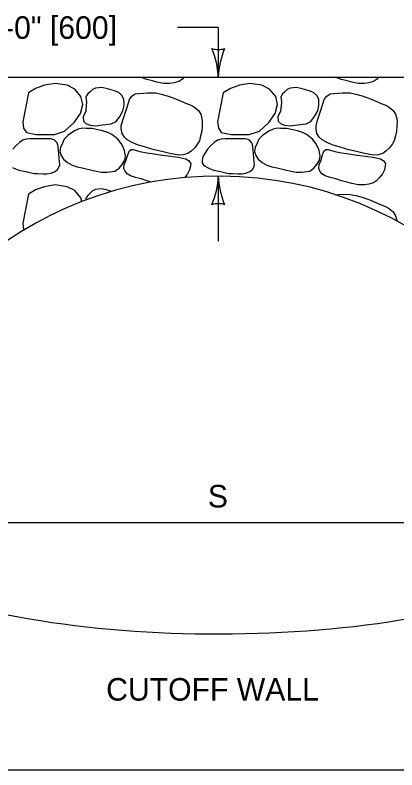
# Model space of a CAD drawing. Extents: x 49991.4 to 50021, y 49987.6 to 50011.4.
# Drawn here: x 50001.991 to 50003.007, y 50007.835 to 50009.843 of the extents above; entities that cross this region are included whole.
import ezdxf

# ---------------------------------------------------------------- set-up
doc = ezdxf.new("R2010")
doc.units = 0
for name, color, linetype in [('Default', 7, 'Continuous'), ('Level 1', 7, 'Continuous'), ('Level 2', 7, 'Continuous'), ('Level 3', 7, 'Continuous')]:
    doc.layers.add(name, color=color, linetype=linetype)

msp = doc.modelspace()

# ---------------------------------------------------------------- linework, layer by layer
at = {"layer": 'Default'}
for points in [[(50002.4399, 50009.6783), (50002.4344, 50009.6723), (50002.4262, 50009.6671), (50002.4139, 50009.6633), (50002.4024, 50009.6611), (50002.386, 50009.6615), (50002.3683, 50009.6648), (50002.3564, 50009.6686), (50002.3412, 50009.6723), (50002.326, 50009.6775), (50002.3229, 50009.6783)], [(50002.9581, 50009.6783), (50002.9526, 50009.6723), (50002.9444, 50009.6671), (50002.9321, 50009.6633), (50002.9206, 50009.6611), (50002.9042, 50009.6615), (50002.8866, 50009.6648), (50002.8747, 50009.6686), (50002.8595, 50009.6723), (50002.8443, 50009.6775), (50002.8412, 50009.6783)], [(50001.9842, 50009.4377), (50001.992, 50009.4347), (50002.001, 50009.4309), (50002.0101, 50009.4287), (50002.0191, 50009.4272), (50002.0298, 50009.4242), (50002.0417, 50009.422), (50002.0515, 50009.422), (50002.0655, 50009.4212), (50002.0757, 50009.4212), (50002.0868, 50009.4227), (50002.0975, 50009.4272), (50002.104, 50009.4324), (50002.1077, 50009.4384), (50002.1098, 50009.4451), (50002.1081, 50009.4627), (50002.1069, 50009.475), (50002.1061, 50009.4839), (50002.1044, 50009.4992), (50002.1008, 50009.5056), (50002.095, 50009.5112), (50002.0852, 50009.5138), (50002.0733, 50009.5142), (50002.0581, 50009.5145), (50002.0429, 50009.5145), (50002.0314, 50009.5145), (50002.0207, 50009.5134), (50002.0113, 50009.5104), (50002.0027, 50009.5041), (50001.9928, 50009.4959), (50001.9846, 50009.4865)], [(50002.3546, 50009.3993), (50002.3412, 50009.4026), (50002.326, 50009.4078), (50002.3109, 50009.4115), (50002.2977, 50009.416), (50002.2891, 50009.4209), (50002.2834, 50009.428), (50002.2805, 50009.4354), (50002.2813, 50009.4459), (50002.2858, 50009.4556), (50002.2899, 50009.4686), (50002.2944, 50009.4813), (50002.2994, 50009.4854), (50002.3055, 50009.4862), (50002.3232, 50009.4809), (50002.3412, 50009.4772), (50002.3552, 50009.475), (50002.3708, 50009.4727), (50002.3831, 50009.4705), (50002.3979, 50009.469), (50002.4245, 50009.4653), (50002.445, 50009.4608), (50002.4524, 50009.4563), (50002.4582, 50009.4489), (50002.4574, 50009.4414), (50002.4553, 50009.4313), (50002.45, 50009.4212), (50002.4426, 50009.4115), (50002.4421, 50009.411)], [(50002.1685, 50009.3471), (50002.1662, 50009.3571), (50002.1498, 50009.3765), (50002.1293, 50009.3869), (50002.0973, 50009.3914), (50002.0694, 50009.3869), (50002.0456, 50009.3787), (50002.0265, 50009.3671), (50002.0185, 50009.3264), (50002.0111, 50009.2899), (50002.0135, 50009.2727), (50002.0143, 50009.2715)], [(50002.2478, 50009.3741), (50002.237, 50009.3772), (50002.2218, 50009.3813), (50002.2046, 50009.3794), (50002.1968, 50009.3757), (50002.1898, 50009.369), (50002.1841, 50009.3638), (50002.1795, 50009.3559), (50002.1801, 50009.3515)], [(50002.8432, 50009.3655), (50002.8517, 50009.3657), (50002.8615, 50009.3668), (50002.8824, 50009.3664), (50002.8976, 50009.3635), (50002.914, 50009.359), (50002.9272, 50009.3545), (50002.9362, 50009.3508), (50002.951, 50009.3448), (50002.9649, 50009.3388), (50002.9793, 50009.3336), (50002.9875, 50009.328), (50002.9973, 50009.3202), (50003.0031, 50009.3097), (50003.0064, 50009.2974), (50003.0065, 50009.2956)]]:
    msp.add_lwpolyline(points, dxfattribs=at)
for points in [[(50002.0265, 50009.6368), (50002.0185, 50009.5962), (50002.0111, 50009.5596), (50002.0135, 50009.5424), (50002.0209, 50009.5312), (50002.0472, 50009.5253), (50002.0956, 50009.5253), (50002.1227, 50009.535), (50002.1481, 50009.5574), (50002.1646, 50009.5813), (50002.1711, 50009.6059), (50002.1662, 50009.6268), (50002.1498, 50009.6462), (50002.1293, 50009.6566), (50002.0973, 50009.6611), (50002.0694, 50009.6566), (50002.0456, 50009.6484)], [(50002.2046, 50009.6492), (50002.1968, 50009.6454), (50002.1898, 50009.6387), (50002.1841, 50009.6335), (50002.1795, 50009.6257), (50002.1812, 50009.6126), (50002.1804, 50009.6033), (50002.1787, 50009.588), (50002.1722, 50009.5727), (50002.1726, 50009.5611), (50002.1787, 50009.5548), (50002.1894, 50009.5503), (50002.205, 50009.5484), (50002.2239, 50009.551), (50002.2468, 50009.554), (50002.26, 50009.5607), (50002.2694, 50009.5738), (50002.278, 50009.5883), (50002.2809, 50009.6029), (50002.2805, 50009.6193), (50002.2752, 50009.6298), (50002.2669, 50009.6376), (50002.255, 50009.6417), (50002.237, 50009.6469), (50002.2218, 50009.651)], [(50002.5448, 50009.6368), (50002.5367, 50009.5962), (50002.5293, 50009.5596), (50002.5318, 50009.5424), (50002.5392, 50009.5312), (50002.5654, 50009.5253), (50002.6139, 50009.5253), (50002.641, 50009.535), (50002.6664, 50009.5574), (50002.6828, 50009.5813), (50002.6894, 50009.6059), (50002.6845, 50009.6268), (50002.668, 50009.6462), (50002.6475, 50009.6566), (50002.6155, 50009.6611), (50002.5876, 50009.6566), (50002.5638, 50009.6484)], [(50002.7228, 50009.6492), (50002.715, 50009.6454), (50002.7081, 50009.6387), (50002.7023, 50009.6335), (50002.6978, 50009.6257), (50002.6994, 50009.6126), (50002.6986, 50009.6033), (50002.697, 50009.588), (50002.6904, 50009.5727), (50002.6908, 50009.5611), (50002.697, 50009.5548), (50002.7076, 50009.5503), (50002.7232, 50009.5484), (50002.7421, 50009.551), (50002.7651, 50009.554), (50002.7782, 50009.5607), (50002.7877, 50009.5738), (50002.7963, 50009.5883), (50002.7992, 50009.6029), (50002.7987, 50009.6193), (50002.7934, 50009.6298), (50002.7852, 50009.6376), (50002.7733, 50009.6417), (50002.7552, 50009.6469), (50002.7401, 50009.651)], [(50002.3194, 50009.6351), (50002.3334, 50009.6354), (50002.3432, 50009.6366), (50002.3642, 50009.6362), (50002.3794, 50009.6332), (50002.3958, 50009.6287), (50002.4089, 50009.6242), (50002.4179, 50009.6205), (50002.4327, 50009.6145), (50002.4467, 50009.6086), (50002.461, 50009.6033), (50002.4692, 50009.5977), (50002.4791, 50009.5899), (50002.4848, 50009.5795), (50002.4881, 50009.5671), (50002.4889, 50009.5589), (50002.4885, 50009.547), (50002.4877, 50009.535), (50002.4844, 50009.522), (50002.4815, 50009.5093), (50002.4766, 50009.5011), (50002.4688, 50009.4899), (50002.4594, 50009.4813), (50002.4508, 50009.4753), (50002.4385, 50009.4716), (50002.4265, 50009.4705), (50002.4023, 50009.4753), (50002.3814, 50009.4809), (50002.3605, 50009.485), (50002.3375, 50009.4921), (50002.3166, 50009.4985), (50002.3026, 50009.5041), (50002.2895, 50009.5112), (50002.2821, 50009.5183), (50002.2755, 50009.5283), (50002.2735, 50009.5406), (50002.2735, 50009.5485), (50002.2776, 50009.5638), (50002.2829, 50009.5798), (50002.2878, 50009.5962), (50002.2928, 50009.6101), (50002.2952, 50009.619), (50002.3018, 50009.6276), (50002.3108, 50009.6339)], [(50002.8377, 50009.6351), (50002.8517, 50009.6354), (50002.8615, 50009.6366), (50002.8824, 50009.6362), (50002.8976, 50009.6332), (50002.914, 50009.6287), (50002.9272, 50009.6242), (50002.9362, 50009.6205), (50002.951, 50009.6145), (50002.9649, 50009.6086), (50002.9793, 50009.6033), (50002.9875, 50009.5977), (50002.9973, 50009.5899), (50003.0031, 50009.5795), (50003.0064, 50009.5671), (50003.0072, 50009.5589), (50003.0068, 50009.547), (50003.0059, 50009.535), (50003.0027, 50009.522), (50002.9998, 50009.5093), (50002.9949, 50009.5011), (50002.9871, 50009.4899), (50002.9776, 50009.4813), (50002.969, 50009.4753), (50002.9567, 50009.4716), (50002.9448, 50009.4705), (50002.9206, 50009.4753), (50002.8997, 50009.4809), (50002.8787, 50009.485), (50002.8558, 50009.4921), (50002.8348, 50009.4985), (50002.8209, 50009.5041), (50002.8077, 50009.5112), (50002.8004, 50009.5183), (50002.7938, 50009.5283), (50002.7917, 50009.5406), (50002.7917, 50009.5485), (50002.7958, 50009.5638), (50002.8012, 50009.5798), (50002.8061, 50009.5962), (50002.811, 50009.6101), (50002.8135, 50009.619), (50002.8201, 50009.6276), (50002.8291, 50009.6339)], [(50002.1492, 50009.5354), (50002.1319, 50009.5239), (50002.1213, 50009.513), (50002.1172, 50009.503), (50002.1114, 50009.4914), (50002.1098, 50009.4809), (50002.1131, 50009.4697), (50002.1196, 50009.4597), (50002.1299, 50009.4511), (50002.1426, 50009.4444), (50002.1562, 50009.4399), (50002.1697, 50009.4369), (50002.1984, 50009.4298), (50002.2202, 50009.4257), (50002.2358, 50009.4253), (50002.2567, 50009.428), (50002.2678, 50009.4358), (50002.276, 50009.4455), (50002.2825, 50009.4574), (50002.2846, 50009.4679), (50002.2817, 50009.4832), (50002.2776, 50009.494), (50002.2727, 50009.5022), (50002.2645, 50009.5134), (50002.2555, 50009.5201), (50002.2485, 50009.5257), (50002.2374, 50009.5306), (50002.2239, 50009.5351), (50002.207, 50009.5392), (50002.196, 50009.5414), (50002.18, 50009.5418), (50002.1701, 50009.5425), (50002.159, 50009.5395)], [(50002.6674, 50009.5354), (50002.6502, 50009.5239), (50002.6395, 50009.513), (50002.6354, 50009.503), (50002.6297, 50009.4914), (50002.628, 50009.4809), (50002.6313, 50009.4697), (50002.6379, 50009.4597), (50002.6481, 50009.4511), (50002.6609, 50009.4444), (50002.6744, 50009.4399), (50002.688, 50009.4369), (50002.7167, 50009.4298), (50002.7384, 50009.4257), (50002.754, 50009.4253), (50002.7749, 50009.428), (50002.786, 50009.4358), (50002.7942, 50009.4455), (50002.8008, 50009.4574), (50002.8029, 50009.4679), (50002.8, 50009.4832), (50002.7959, 50009.494), (50002.791, 50009.5022), (50002.7827, 50009.5134), (50002.7737, 50009.5201), (50002.7667, 50009.5257), (50002.7557, 50009.5306), (50002.7421, 50009.5351), (50002.7253, 50009.5392), (50002.7142, 50009.5414), (50002.6982, 50009.5418), (50002.6884, 50009.5425), (50002.6773, 50009.5395)], [(50002.539, 50009.5134), (50002.5295, 50009.5104), (50002.5209, 50009.5041), (50002.5111, 50009.4959), (50002.5029, 50009.4865), (50002.4963, 50009.4772), (50002.4902, 50009.466), (50002.4889, 50009.4571), (50002.4889, 50009.4507), (50002.4914, 50009.4459), (50002.4967, 50009.4418), (50002.5025, 50009.4377), (50002.5103, 50009.4347), (50002.5193, 50009.4309), (50002.5283, 50009.4287), (50002.5373, 50009.4272), (50002.548, 50009.4242), (50002.5599, 50009.422), (50002.5698, 50009.422), (50002.5837, 50009.4212), (50002.594, 50009.4212), (50002.6051, 50009.4227), (50002.6157, 50009.4272), (50002.6223, 50009.4324), (50002.626, 50009.4384), (50002.628, 50009.4451), (50002.6264, 50009.4627), (50002.6252, 50009.475), (50002.6243, 50009.4839), (50002.6227, 50009.4992), (50002.619, 50009.5056), (50002.6133, 50009.5112), (50002.6034, 50009.5138), (50002.5915, 50009.5142), (50002.5763, 50009.5145), (50002.5611, 50009.5145), (50002.5497, 50009.5145)], [(50002.8127, 50009.4813), (50002.8176, 50009.4854), (50002.8238, 50009.4862), (50002.8414, 50009.4809), (50002.8595, 50009.4772), (50002.8734, 50009.475), (50002.889, 50009.4727), (50002.9013, 50009.4705), (50002.9161, 50009.469), (50002.9428, 50009.4653), (50002.9633, 50009.4608), (50002.9707, 50009.4563), (50002.9764, 50009.4489), (50002.9756, 50009.4414), (50002.9736, 50009.4313), (50002.9682, 50009.4212), (50002.9608, 50009.4115), (50002.9526, 50009.4026), (50002.9444, 50009.3974), (50002.9321, 50009.3936), (50002.9206, 50009.3914), (50002.9042, 50009.3918), (50002.8866, 50009.3951), (50002.8747, 50009.3988), (50002.8595, 50009.4026), (50002.8443, 50009.4078), (50002.8291, 50009.4115), (50002.816, 50009.416), (50002.8074, 50009.4209), (50002.8016, 50009.428), (50002.7987, 50009.4354), (50002.7996, 50009.4459), (50002.8041, 50009.4556), (50002.8082, 50009.4686)]]:
    msp.add_lwpolyline(points, close=True, dxfattribs=at)
at = {"layer": 'Level 1'}
for p, q in [((50001.0174, 50009.6783), (50004.0457, 50009.6783)), ((50001.0174, 50007.8352), (50004.0457, 50007.8352))]:
    msp.add_line(p, q, dxfattribs=at)
msp.add_arc((50002.5316, 50008.4111), 1.004, 4.6997, 174.3593, dxfattribs=at)
msp.add_ellipse((50002.5316, 50008.4934), major_axis=(1.0006, 0), ratio=0.296155, start_param=3.086438, end_param=6.282899, dxfattribs=at)
at = {"layer": 'Level 3'}
for p, q in [((50002.5316, 50009.8102), (50002.4227, 50009.8102)), ((50002.5316, 50009.8102), (50002.5316, 50009.6783)), ((50002.5316, 50009.415), (50002.5316, 50009.2416)), ((50001.531, 50008.4934), (50003.5322, 50008.4934))]:
    msp.add_line(p, q, dxfattribs=at)
for centre, radius, start, end in [((50002.5316, 50009.8065), 0.0548, 252.1388, 287.8612), ((50002.2989, 50009.6668), 0.233, 2.8273, 22.0772), ((50002.7537, 50009.6691), 0.2223, 157.456, 177.6395), ((50002.3095, 50009.4242), 0.2223, 337.456, 357.6395), ((50002.7643, 50009.4265), 0.233, 182.8273, 202.0772), ((50002.5316, 50009.2868), 0.0548, 72.1388, 107.8612)]:
    msp.add_arc(centre, radius, start, end, dxfattribs=at)

# ---------------------------------------------------------------- texts
at = {"layer": 'Level 2'}
for s, p in [('2\'-0" [600]', (50001.9015, 50009.7802)), ('S', (50002.5038, 50008.5334)), ('CUTOFF WALL', (50002.2332, 50008.0195))]:
    msp.add_text(s, height=0.06, dxfattribs=at).set_placement(p)

doc.saveas('drawing.dxf')
